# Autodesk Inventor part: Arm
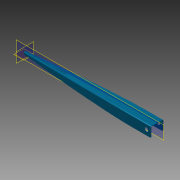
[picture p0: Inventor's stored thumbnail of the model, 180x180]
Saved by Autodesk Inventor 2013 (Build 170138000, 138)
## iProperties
Created: 2006-03
Part Number: Arm
Document SubType Name: Modeling
Designer: debonom
Material: Stainless Steel, 440C
Mass: 106.754 g
Surface Area: 286.718 cm^2
Volume: 13.7747 cm^3
Density: 7.75 g/cm^3
Author: debonom
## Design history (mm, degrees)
sketch "Sketch1"
  geometry: L1 (-13.5, 11)-(13.5, 11); L2 (13.5, 11)-(13.5, -11); L3 (13.5, -11)-(-13.5, -11); L4 (-13.5, -11)-(-13.5, 11); L5 (-13.5, 11)-(13.5, -11); 2 further points
  constraints: 10 end point, 2 parallel, 1 coincident, 1 horizontal, 1 midpoint, 1 perpendicular
  dimensions: "d0" = 27 distance of L1.start L1.end; "d1" = 22 distance of L3.end L1.start
extrude "Extrusion1" new body sketch "Sketch1" distance "d2" = 40; taper "d3" = 0 deg
workplane "Work Plane1"
sketch "Sketch2"
  geometry: L1 (-2.5, 2.5)-(2.5, 2.5); L2 (2.5, 2.5)-(2.5, -2.5); L3 (2.5, -2.5)-(-2.5, -2.5); L4 (-2.5, -2.5)-(-2.5, 2.5); L5 (-2.5, 2.5)-(2.5, -2.5); 2 further points
  constraints: 10 end point, 2 parallel, 2 perpendicular, 1 coincident, 1 horizontal, 1 midpoint
  dimensions: "d5" = 5 distance of L1.start L1.end
loft "Loft1" sketch "Sketch2" dims "d6" = 10, "d7" = 90 deg, "d8" = 10, "d9" = 90 deg
  node "Edges1"
shell "Shell1" dims "d10" = 1
sketch "Sketch3"
  geometry: L1 (-48, 0)-(8, 0) reference; L2 (-40, 10)-(-40, -11) reference; C1 r 4 at (-30, 0); 1 further point
  constraints: 1 centre point, 1 point on line
  dimensions: "d11" = 10 distance from line of C1.centre L2; "d16" = 8 diameter of C1
extrude "Extrusion2" cut sketch "Sketch3" stored distance "d12" = 40; taper "d13" = 0 deg
fillet "Fillet1" dims "d14" = 2
fillet "Fillet2" dims "d15" = 2
workplane "Work Plane2"
workplane "Work Plane3"
body "Solid1"
